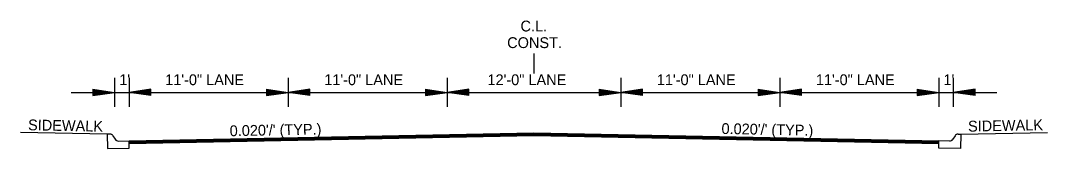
# Model space of a CAD drawing. Extents: x 550980 to 1930787, y -1972975 to 596640.
# Drawn here: x 551196 to 551906, y -1968352 to -1968263 of the extents above; entities that cross this region are included whole.
import ezdxf

# ---------------------------------------------------------------- set-up
doc = ezdxf.new("R2010")
doc.units = 0
doc.layers.add('R_Border', color=7, linetype='Continuous')
doc.layers.add('R_Draft', color=7, linetype='Continuous')

msp = doc.modelspace()

# ---------------------------------------------------------------- linework, layer by layer
at = {"layer": 'R_Border'}
for p, q in [((551551.08, -1968285.73), (551551.08, -1968299.73)), ((551261.08, -1968302.73), (551261.08, -1968322.73)), ((551271.08, -1968302.73), (551271.08, -1968322.73)), ((551381.08, -1968302.73), (551381.08, -1968322.73)), ((551491.08, -1968302.73), (551491.08, -1968322.73)), ((551611.08, -1968302.73), (551611.08, -1968322.73)), ((551721.08, -1968302.73), (551721.08, -1968322.73)), ((551831.08, -1968302.73), (551831.08, -1968322.73)), ((551841.08, -1968302.73), (551841.08, -1968322.73)), ((551231.08, -1968312.73), (551871.08, -1968312.73)), ((551246.08, -1968310.48), (551261.08, -1968312.73)), ((551246.08, -1968310.48), (551246.08, -1968314.98)), ((551246.08, -1968310.86), (551258.58, -1968312.73)), ((551246.08, -1968311.24), (551256, -1968312.73)), ((551246.08, -1968311.62), (551253.5, -1968312.73)), ((551246.08, -1968312.01), (551250.96, -1968312.73)), ((551246.08, -1968312.38), (551248.45, -1968312.73)), ((551246.08, -1968314.98), (551261.08, -1968312.73)), ((551246.08, -1968313.47), (551250.96, -1968312.73)), ((551246.08, -1968314.23), (551256, -1968312.73)), ((551246.08, -1968314.61), (551258.58, -1968312.73)), ((551246.08, -1968313.85), (551253.5, -1968312.73)), ((551246.08, -1968313.09), (551248.45, -1968312.73)), ((551286.08, -1968310.48), (551271.08, -1968312.73)), ((551286.08, -1968314.98), (551271.08, -1968312.73)), ((551286.08, -1968310.86), (551273.59, -1968312.73)), ((551286.08, -1968314.61), (551273.59, -1968312.73)), ((551286.08, -1968311.24), (551276.17, -1968312.73)), ((551286.08, -1968314.23), (551276.17, -1968312.73)), ((551286.08, -1968311.62), (551278.67, -1968312.73)), ((551286.08, -1968313.85), (551278.67, -1968312.73)), ((551286.08, -1968312), (551281.21, -1968312.73)), ((551286.08, -1968313.46), (551281.21, -1968312.73)), ((551286.08, -1968312.38), (551283.71, -1968312.73)), ((551286.08, -1968313.09), (551283.71, -1968312.73)), ((551286.08, -1968314.98), (551286.08, -1968310.48)), ((551366.08, -1968310.48), (551381.08, -1968312.73)), ((551366.08, -1968310.48), (551366.08, -1968314.98)), ((551366.08, -1968310.86), (551378.58, -1968312.73)), ((551366.08, -1968311.24), (551376, -1968312.73)), ((551366.08, -1968311.62), (551373.5, -1968312.73)), ((551366.08, -1968312.01), (551370.96, -1968312.73)), ((551366.08, -1968312.38), (551368.45, -1968312.73)), ((551366.08, -1968314.98), (551381.08, -1968312.73)), ((551366.08, -1968313.47), (551370.96, -1968312.73)), ((551366.08, -1968314.23), (551376, -1968312.73)), ((551366.08, -1968314.61), (551378.58, -1968312.73)), ((551366.08, -1968313.85), (551373.5, -1968312.73)), ((551366.08, -1968313.09), (551368.45, -1968312.73)), ((551396.08, -1968310.48), (551381.08, -1968312.73)), ((551396.08, -1968314.98), (551381.08, -1968312.73)), ((551396.08, -1968310.86), (551383.59, -1968312.73)), ((551396.08, -1968314.61), (551383.59, -1968312.73)), ((551396.08, -1968311.24), (551386.17, -1968312.73)), ((551396.08, -1968314.23), (551386.17, -1968312.73)), ((551396.08, -1968311.62), (551388.67, -1968312.73)), ((551396.08, -1968313.85), (551388.67, -1968312.73)), ((551396.08, -1968312), (551391.21, -1968312.73)), ((551396.08, -1968313.46), (551391.21, -1968312.73)), ((551396.08, -1968312.38), (551393.71, -1968312.73)), ((551396.08, -1968313.09), (551393.71, -1968312.73)), ((551396.08, -1968314.98), (551396.08, -1968310.48)), ((551476.08, -1968310.48), (551491.08, -1968312.73)), ((551476.08, -1968310.48), (551476.08, -1968314.98)), ((551476.08, -1968310.86), (551488.58, -1968312.73)), ((551476.08, -1968311.24), (551486, -1968312.73)), ((551476.08, -1968311.62), (551483.5, -1968312.73)), ((551476.08, -1968312.01), (551480.96, -1968312.73)), ((551476.08, -1968312.38), (551478.45, -1968312.73)), ((551476.08, -1968314.98), (551491.08, -1968312.73)), ((551476.08, -1968313.47), (551480.96, -1968312.73)), ((551476.08, -1968314.23), (551486, -1968312.73)), ((551476.08, -1968314.61), (551488.58, -1968312.73)), ((551476.08, -1968313.85), (551483.5, -1968312.73)), ((551476.08, -1968313.09), (551478.45, -1968312.73)), ((551506.08, -1968310.48), (551491.08, -1968312.73)), ((551506.08, -1968314.98), (551491.08, -1968312.73)), ((551506.08, -1968310.86), (551493.59, -1968312.73)), ((551506.08, -1968314.61), (551493.59, -1968312.73)), ((551506.08, -1968311.24), (551496.17, -1968312.73)), ((551506.08, -1968314.23), (551496.17, -1968312.73)), ((551506.08, -1968311.62), (551498.67, -1968312.73)), ((551506.08, -1968313.85), (551498.67, -1968312.73)), ((551506.08, -1968312), (551501.21, -1968312.73)), ((551506.08, -1968313.46), (551501.21, -1968312.73)), ((551506.08, -1968312.38), (551503.71, -1968312.73)), ((551506.08, -1968313.09), (551503.71, -1968312.73)), ((551506.08, -1968314.98), (551506.08, -1968310.48)), ((551596.08, -1968310.48), (551611.08, -1968312.73)), ((551596.08, -1968310.48), (551596.08, -1968314.98)), ((551596.08, -1968310.86), (551608.58, -1968312.73)), ((551596.08, -1968311.24), (551606, -1968312.73)), ((551596.08, -1968311.62), (551603.5, -1968312.73)), ((551596.08, -1968312.01), (551600.96, -1968312.73)), ((551596.08, -1968312.38), (551598.45, -1968312.73)), ((551596.08, -1968314.98), (551611.08, -1968312.73)), ((551596.08, -1968313.47), (551600.96, -1968312.73)), ((551596.08, -1968314.23), (551606, -1968312.73)), ((551596.08, -1968314.61), (551608.58, -1968312.73)), ((551596.08, -1968313.85), (551603.5, -1968312.73)), ((551596.08, -1968313.09), (551598.45, -1968312.73)), ((551626.08, -1968310.48), (551611.08, -1968312.73)), ((551626.08, -1968314.98), (551611.08, -1968312.73)), ((551626.08, -1968310.86), (551613.59, -1968312.73)), ((551626.08, -1968314.61), (551613.59, -1968312.73)), ((551626.08, -1968311.24), (551616.17, -1968312.73)), ((551626.08, -1968314.23), (551616.17, -1968312.73)), ((551626.08, -1968311.62), (551618.67, -1968312.73)), ((551626.08, -1968313.85), (551618.67, -1968312.73)), ((551626.08, -1968312), (551621.21, -1968312.73)), ((551626.08, -1968313.46), (551621.21, -1968312.73)), ((551626.08, -1968312.38), (551623.71, -1968312.73)), ((551626.08, -1968313.09), (551623.71, -1968312.73)), ((551626.08, -1968314.98), (551626.08, -1968310.48)), ((551706.08, -1968310.48), (551721.08, -1968312.73)), ((551706.08, -1968310.48), (551706.08, -1968314.98)), ((551706.08, -1968310.86), (551718.58, -1968312.73)), ((551706.08, -1968311.24), (551716, -1968312.73)), ((551706.08, -1968311.62), (551713.5, -1968312.73)), ((551706.08, -1968312.01), (551710.96, -1968312.73)), ((551706.08, -1968312.38), (551708.45, -1968312.73)), ((551706.08, -1968314.98), (551721.08, -1968312.73)), ((551706.08, -1968313.47), (551710.96, -1968312.73)), ((551706.08, -1968314.23), (551716, -1968312.73)), ((551706.08, -1968314.61), (551718.58, -1968312.73)), ((551706.08, -1968313.85), (551713.5, -1968312.73)), ((551706.08, -1968313.09), (551708.45, -1968312.73)), ((551736.08, -1968310.48), (551721.08, -1968312.73)), ((551736.08, -1968314.98), (551721.08, -1968312.73)), ((551736.08, -1968310.86), (551723.59, -1968312.73)), ((551736.08, -1968314.61), (551723.59, -1968312.73)), ((551736.08, -1968311.24), (551726.17, -1968312.73)), ((551736.08, -1968314.23), (551726.17, -1968312.73)), ((551736.08, -1968311.62), (551728.67, -1968312.73)), ((551736.08, -1968313.85), (551728.67, -1968312.73)), ((551736.08, -1968312), (551731.21, -1968312.73)), ((551736.08, -1968313.46), (551731.21, -1968312.73)), ((551736.08, -1968312.38), (551733.71, -1968312.73)), ((551736.08, -1968313.09), (551733.71, -1968312.73)), ((551736.08, -1968314.98), (551736.08, -1968310.48)), ((551816.08, -1968310.48), (551831.08, -1968312.73)), ((551816.08, -1968310.48), (551816.08, -1968314.98)), ((551816.08, -1968310.86), (551828.58, -1968312.73)), ((551816.08, -1968311.24), (551826, -1968312.73)), ((551816.08, -1968311.62), (551823.5, -1968312.73)), ((551816.08, -1968312.01), (551820.96, -1968312.73)), ((551816.08, -1968312.38), (551818.45, -1968312.73)), ((551816.08, -1968314.98), (551831.08, -1968312.73)), ((551816.08, -1968313.47), (551820.96, -1968312.73)), ((551816.08, -1968314.23), (551826, -1968312.73)), ((551816.08, -1968314.61), (551828.58, -1968312.73)), ((551816.08, -1968313.85), (551823.5, -1968312.73)), ((551816.08, -1968313.09), (551818.45, -1968312.73)), ((551856.08, -1968310.48), (551841.08, -1968312.73)), ((551856.08, -1968314.98), (551841.08, -1968312.73)), ((551856.08, -1968310.86), (551843.59, -1968312.73)), ((551856.08, -1968314.61), (551843.59, -1968312.73)), ((551856.08, -1968311.24), (551846.17, -1968312.73)), ((551856.08, -1968314.23), (551846.17, -1968312.73)), ((551856.08, -1968311.62), (551848.67, -1968312.73)), ((551856.08, -1968313.85), (551848.67, -1968312.73)), ((551856.08, -1968312), (551851.21, -1968312.73)), ((551856.08, -1968313.46), (551851.21, -1968312.73)), ((551856.08, -1968312.38), (551853.71, -1968312.73)), ((551856.08, -1968313.09), (551853.71, -1968312.73)), ((551856.08, -1968314.98), (551856.08, -1968310.48)), ((551255.99, -1968341.63), (551195.99, -1968340.43)), ((551846.18, -1968341.63), (551906.18, -1968340.43))]:
    msp.add_line(p, q, dxfattribs=at)
for points in [[(551271.08, -1968346.33), (551551.08, -1968340.73), (551831.08, -1968346.33)], [(551271.08, -1968346.63), (551551.08, -1968341.03), (551831.08, -1968346.63)], [(551271.08, -1968346.93), (551551.08, -1968341.33), (551831.08, -1968346.93)], [(551271.08, -1968347.23), (551551.08, -1968341.63), (551831.08, -1968347.23)], [(551271.08, -1968347.53), (551551.08, -1968341.93), (551831.08, -1968347.53)], [(551271.08, -1968347.83), (551551.08, -1968342.23), (551831.08, -1968347.83)], [(551271.08, -1968348.13), (551551.08, -1968342.53), (551831.08, -1968348.13)]]:
    msp.add_lwpolyline(points, dxfattribs=at)
at = {"layer": 'R_Draft'}
for p, q in [((551257.72, -1968341.6), (551255.99, -1968341.63)), ((551259.92, -1968342.81), (551261.39, -1968345.27)), ((551842.25, -1968342.81), (551840.78, -1968345.27)), ((551844.44, -1968341.6), (551846.18, -1968341.63)), ((551263.59, -1968346.48), (551271.08, -1968346.33)), ((551838.58, -1968346.48), (551831.08, -1968346.33))]:
    msp.add_line(p, q, dxfattribs=at)
for points in [[(551255.99, -1968341.63), (551256.19, -1968351.63), (551271.08, -1968351.33), (551271.08, -1968346.33)], [(551846.18, -1968341.63), (551845.98, -1968351.63), (551831.08, -1968351.33), (551831.08, -1968346.33)]]:
    msp.add_lwpolyline(points, dxfattribs=at)
for centre, start, end in [((551257.77, -1968344.1), 30.94405, 91.14576), ((551844.39, -1968344.1), 88.85424, 149.05595), ((551263.54, -1968343.98), 210.94405, 271.14576), ((551838.63, -1968343.98), 268.85424, 329.05595)]:
    msp.add_arc(centre, 2.5, start, end, dxfattribs=at)

# ---------------------------------------------------------------- texts
at = {"layer": 'R_Border'}
for s, p in [('C.L.', (551541.75, -1968270.52)), ('CONST.', (551532.54, -1968282.02)), ("1'", (551264.25, -1968307.73)), ('11\'-0" LANE', (551296.02, -1968307.73)), ('11\'-0" LANE', (551406.02, -1968307.73)), ('12\'-0" LANE', (551518.9, -1968307.73)), ('11\'-0" LANE', (551636.02, -1968307.73)), ('11\'-0" LANE', (551746.02, -1968307.73)), ("1'", (551834.25, -1968307.73))]:
    msp.add_text(s, height=7.5, dxfattribs=at).set_placement(p)
for s, rotation, p in [('SIDEWALK', 358.8542, (551201.13, -1968338.98)), ("0.020'/' (TYP.)", 1.1458, (551340.7, -1968343.14)), ("0.020'/' (TYP.)", 358.8542, (551680.7, -1968341.53)), ('SIDEWALK', 1.1458, (551851.32, -1968339.97))]:
    msp.add_text(s, height=7.5, rotation=rotation, dxfattribs=at).set_placement(p)

doc.saveas('drawing.dxf')
